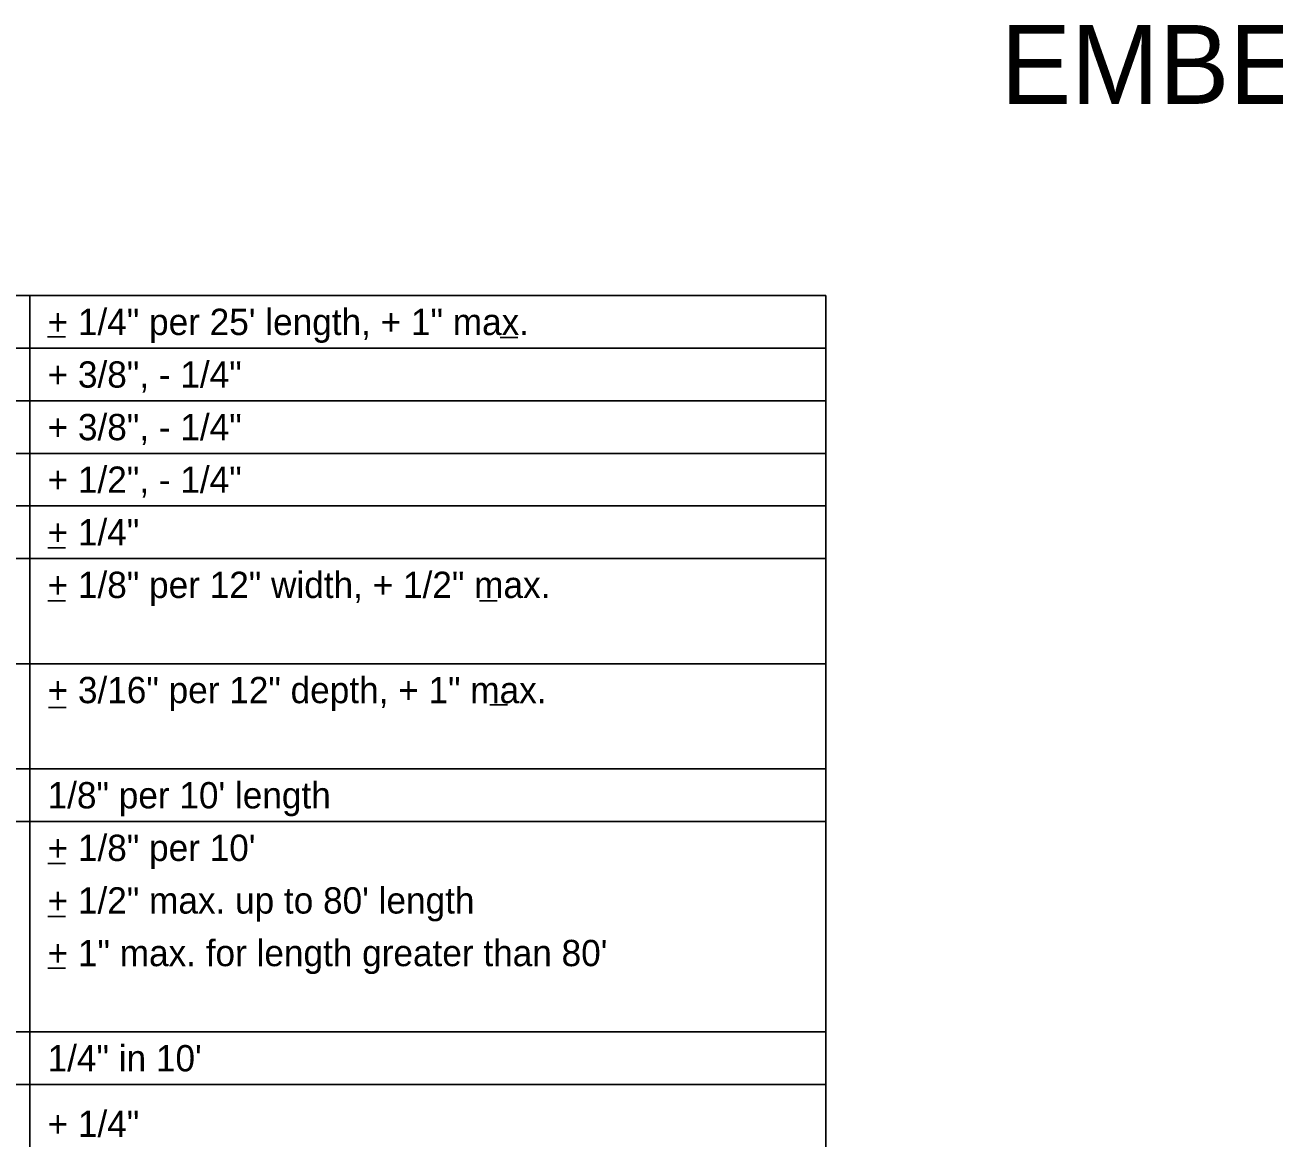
# Model space of a CAD drawing. Extents: x -50.5 to -14.4, y 42.4 to 64.4.
# Drawn here: x -29.12 to -23.18, y 47.94 to 53.23 of the extents above; entities that cross this region are included whole.
import ezdxf

# ---------------------------------------------------------------- set-up
doc = ezdxf.new("R2010")
doc.units = 0
for name, color, linetype in [('BR_BORDER LINES', 7, 'Continuous'), ('BR_TABLE LINES', 7, 'Continuous'), ('BR_TEXT', 7, 'Continuous')]:
    doc.layers.add(name, color=color, linetype=linetype)

msp = doc.modelspace()

# ---------------------------------------------------------------- linework, layer by layer
at = {"layer": 'BR_BORDER LINES'}
for p, q in [((-33.6075, 51.9486), (-25.3179, 51.9486)), ((-25.3179, 51.9486), (-25.3179, 45.6987))]:
    msp.add_line(p, q, dxfattribs=at)
at = {"layer": 'BR_TABLE LINES'}
for p, q in [((-29.1004, 51.9486), (-29.1004, 42.9486)), ((-33.6075, 51.6986), (-25.3179, 51.6986)), ((-33.6075, 51.4486), (-25.3179, 51.4486)), ((-33.6075, 51.1986), (-25.3179, 51.1986)), ((-33.6075, 50.9486), (-25.3179, 50.9486)), ((-33.6075, 50.6986), (-25.3179, 50.6986)), ((-33.6075, 50.1986), (-25.3179, 50.1986)), ((-33.6075, 49.6986), (-25.3179, 49.6986)), ((-33.6075, 49.4486), (-25.3179, 49.4486)), ((-33.6075, 48.4486), (-25.3179, 48.4486)), ((-33.6075, 48.1986), (-25.3179, 48.1986))]:
    msp.add_line(p, q, dxfattribs=at)
at = {"layer": 'BR_TEXT'}
for p, q in [((-29.0161, 51.7532), (-28.9314, 51.7532)), ((-26.8652, 51.7492), (-26.7805, 51.7492)), ((-29.0153, 50.7489), (-28.9306, 50.7489)), ((-29.0153, 50.4972), (-28.9306, 50.4972)), ((-26.9632, 50.4972), (-26.8785, 50.4972)), ((-29.0121, 49.9907), (-28.9274, 49.9907)), ((-26.9148, 50.0036), (-26.8301, 50.0036)), ((-29.0153, 49.2486), (-28.9306, 49.2486)), ((-29.0153, 48.9969), (-28.9306, 48.9969)), ((-29.0153, 48.7517), (-28.9306, 48.7517))]:
    msp.add_line(p, q, dxfattribs=at)

# ---------------------------------------------------------------- texts
for s, height, p in [('EMBEDDED PLATE DETAIL', 0.375, (-24.4863, 52.8599)), ('+ 1/4" per 25\' length, + 1" max.', 0.125, (-29.0157, 51.7611)), ('+ 3/8", - 1/4"', 0.125, (-29.0157, 51.5111)), ('+ 3/8", - 1/4"', 0.125, (-29.0157, 51.2611)), ('+ 1/2", - 1/4"', 0.125, (-29.0157, 51.0111)), ('+ 1/4"', 0.125, (-29.0157, 50.7611)), ('+ 1/8" per 12" width, + 1/2" max.', 0.125, (-29.0157, 50.5111)), ('+ 3/16" per 12" depth, + 1" max.', 0.125, (-29.0157, 50.0111)), ('1/8" per 10\' length', 0.125, (-29.0157, 49.5111)), ('+ 1/8" per 10\'', 0.125, (-29.0157, 49.2611)), ('+ 1/2" max. up to 80\' length', 0.125, (-29.0157, 49.0111)), ('+ 1" max. for length greater than 80\'', 0.125, (-29.0157, 48.7611)), ('1/4" in 10\'', 0.125, (-29.0157, 48.2611)), ('+ 1/4"', 0.125, (-29.0157, 47.9492))]:
    msp.add_text(s, height=height, dxfattribs=at).set_placement(p)

doc.saveas('drawing.dxf')
